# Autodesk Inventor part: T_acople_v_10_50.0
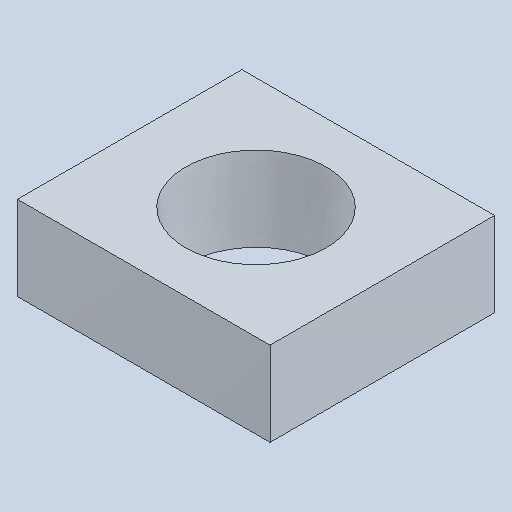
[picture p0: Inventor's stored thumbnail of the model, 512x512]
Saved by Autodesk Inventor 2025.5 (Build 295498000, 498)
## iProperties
Created: 2026-10
Part Number: T_acople_v_10_50.0
Material: Genérico
Document SubType Name: Modeling
Designer: Luis M
Density: 1 g/cm^3
Appearance: Valor por defecto
Author: Luis M
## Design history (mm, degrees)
feature "Base1"
node "Sólido1"
